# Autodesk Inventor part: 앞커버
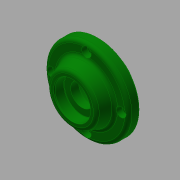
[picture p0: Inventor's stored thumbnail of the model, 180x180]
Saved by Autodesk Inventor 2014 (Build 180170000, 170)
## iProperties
Created: 2017-08
Part Number: 앞커버
Material: 알루미늄 6061
Document SubType Name: Modeling
Designer: mduedu
Density: 1 g/cm^3
Appearance: 진녹색
Author: mduedu
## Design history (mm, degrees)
sketch "스케치1"
  geometry: C1 r 35 at (0, 0); 1 further point
  constraints: 1 centre point, 1 coincident
  dimensions: "d0" = 70 diameter of C1
extrude "돌출1" new body sketch "스케치1" distance "d1" = 10; taper "d2" = 0 deg
sketch "스케치2"
  geometry: C1 r 24 at (0, 0); 1 further point
  constraints: 1 centre point, 1 coincident
  dimensions: "d3" = 48 diameter of C1
node "작업 평면1"
sketch "스케치3"
  geometry: C1 r 20 at (0, 0); 1 further point
  constraints: 1 centre point, 1 coincident
  dimensions: "d5" = 40 diameter of C1
feature "로프트1" sketch "스케치3" dims "d6" = 0, "d7" = 90 deg, "d8" = 0, "d9" = 90 deg
sketch "스케치4"
  geometry: C1 r 24 at (0, 0) reference; 1 further point
extrude "돌출2" join sketch "스케치4" distance "d10" = 8; taper "d11" = 0 deg
hole "구멍1" diameter "d14" = 40; stored, may be unused: countersink angle "d18" = 90 deg, drill point angle "d20" = 0 deg; dims "d12" = 10, "d13" = 10, "d15" = 6, "d16" = 4, "d17" = 2, "d19" = 12
hole "구멍2" diameter "d23" = 34; stored, may be unused: countersink angle "d27" = 90 deg, drill point angle "d29" = 0 deg; dims "d21" = 10, "d22" = 10, "d24" = 6, "d25" = 4, "d26" = 2, "d28" = 3
hole "구멍3" diameter "d32" = 19; stored, may be unused: countersink angle "d36" = 90 deg, drill point angle "d38" = 0 deg; dims "d30" = 10, "d31" = 10, "d33" = 6, "d34" = 4, "d35" = 2, "d37" = 3
chamfer "모따기1" distance "d39" = 1; stored, may be unused: second distance "d40" = 2, angle "d41" = 45 deg
sketch "스케치5"
  geometry: C1 r 15 at (0, 0); 1 further point
  constraints: 1 centre point, 1 coincident
  dimensions: "d42" = 30 diameter of C1
extrude "돌출3" cut sketch "스케치5" distance "d43" = 8.3; taper "d44" = 0 deg
chamfer "모따기2" distance "d47" = 0.8; stored, may be unused: second distance "d48" = 2, angle "d49" = 30 deg
fillet "모깎기1" dims "d50" = 0.3
fillet "모깎기2" dims "d51" = 0.3
fillet "모깎기3" dims "d52" = 3
sketch "스케치6" dims "d53" = 58
  geometry: 6 further points
  constraints: 2 vertical alignment, 1 coincident, 7 other
  dimensions: "d56" = 360 deg dimension on point (0, 0) point (0, 29) (derived)
sketch "스케치9"
  geometry: 4 further points
  constraints: 4 other
hole "구멍6" sketch "스케치9" at (-29, 0), (0, -29), (29, 0), (0, 29) diameter "d72" = 4.5; stored, may be unused: countersink angle "d76" = 90 deg, drill point angle "d78" = 0 deg; dims "d73" = 6, "d74" = 8, "d75" = 4.6, "d77" = 8
fillet "모깎기4" dims "d79" = 3
fillet "모깎기5" dims "d80" = 3
fillet "모깎기6" dims "d81" = 3
chamfer "모따기3" distance "d82" = 1; stored, may be unused: second distance "d83" = 2, angle "d84" = 30 deg
node "솔리드1"
other parameters: "d4" = 12
